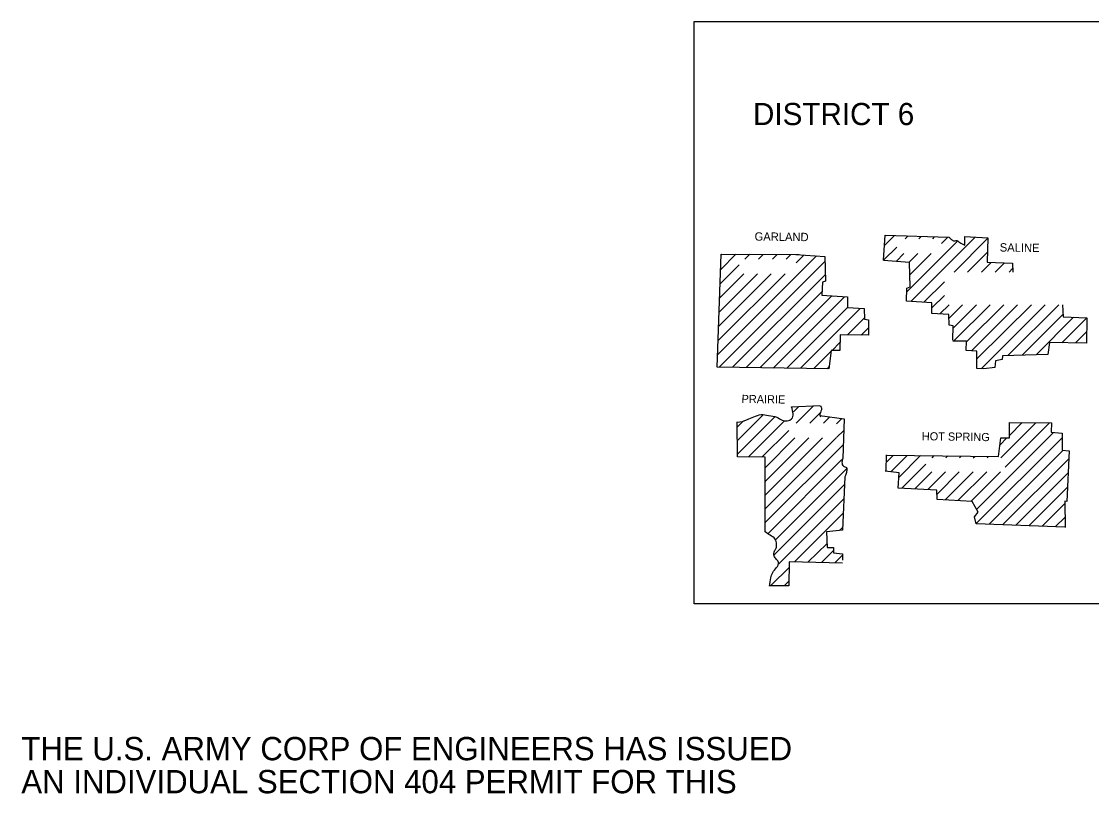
# Model space of a CAD drawing. Extents: x 1366406 to 1373462, y 376856 to 381998.
# Drawn here: x 1371174 to 1371725, y 379841 to 380238 of the extents above; entities that cross this region are included whole.
import ezdxf

# ---------------------------------------------------------------- set-up
doc = ezdxf.new("R2010")
doc.units = 0
doc.layers.add('R_Draft', color=7, linetype='Continuous')

msp = doc.modelspace()

# ---------------------------------------------------------------- linework, layer by layer
at = {"layer": 'R_Draft'}
for p, q in [((1371659.21, 380123.18), (1371659.21, 380127.58)), ((1371625.41, 380005.98), (1371618.31, 380006.68))]:
    msp.add_line(p, q, dxfattribs=at)
msp.add_lwpolyline([(1371519.91, 379938.38), (1371519.91, 380238.38), (1371919.91, 380238.38), (1371919.91, 379938.38)], close=True, dxfattribs=at)
for points in [[(1371617.41, 380115.38), (1371618.31, 380128.28), (1371651.01, 380127.28)], [(1371617.91, 380122.98), (1371623.11, 380128.18)], [(1371628.51, 380126.48), (1371630.01, 380127.98)], [(1371629.41, 380099.08), (1371655.41, 380125.18)], [(1371631.61, 380094.28), (1371664.51, 380127.18)], [(1371635.61, 380126.48), (1371636.71, 380127.68)], [(1371642.71, 380126.48), (1371643.61, 380127.48)], [(1371647.31, 380124.08), (1371650.51, 380127.28)], [(1371653.71, 380109.28), (1371671.01, 380126.58)], [(1371659.21, 380127.58), (1371671.11, 380126.88), (1371670.71, 380114.38), (1371683.81, 380113.88), (1371683.91, 380109.28)], [(1371659.21, 380123.18), (1371659.21, 380123.08)], [(1371531.71, 380060.28), (1371533.91, 380118.58), (1371573.91, 380118.38)], [(1371532.01, 380066.68), (1371582.91, 380117.58)], [(1371533.61, 380110.68), (1371541.41, 380118.48)], [(1371533.91, 380117.98), (1371534.41, 380118.58)], [(1371546.01, 380115.98), (1371548.51, 380118.48)], [(1371553.11, 380115.98), (1371555.51, 380118.38)], [(1371560.21, 380115.98), (1371562.61, 380118.38)], [(1371567.21, 380115.98), (1371569.61, 380118.38)], [(1371572.31, 380118.38), (1371587.21, 380117.28), (1371587.61, 380104.68), (1371585.91, 380104.08), (1371585.71, 380097.38), (1371598.81, 380096.48), (1371598.81, 380090.98), (1371607.51, 380090.48), (1371607.61, 380084.98), (1371609.71, 380084.68), (1371609.61, 380076.78)], [(1371572.41, 380114.08), (1371576.31, 380117.98)], [(1371617.41, 380115.38), (1371624.21, 380122.18)], [(1371623.91, 380114.78), (1371627.91, 380118.78)], [(1371630.51, 380114.28), (1371635.01, 380118.78)], [(1371631.01, 380107.78), (1371642.01, 380118.78)], [(1371660.71, 380109.28), (1371670.81, 380119.38)], [(1371532.71, 380060.28), (1371587.21, 380114.78)], [(1371533.41, 380103.38), (1371543.01, 380112.98)], [(1371653.11, 380074.28), (1371653.21, 380081.68), (1371651.11, 380081.98), (1371651.01, 380087.48), (1371642.31, 380087.98), (1371642.31, 380093.48), (1371629.21, 380094.38), (1371629.41, 380101.08), (1371631.11, 380101.68), (1371630.71, 380114.28), (1371617.41, 380115.28)], [(1371667.91, 380109.28), (1371672.81, 380114.28)], [(1371674.91, 380109.28), (1371679.71, 380114.08)], [(1371532.31, 380073.98), (1371566.71, 380108.38)], [(1371532.51, 380081.28), (1371559.61, 380108.38)], [(1371532.81, 380088.68), (1371552.61, 380108.38)], [(1371533.11, 380095.98), (1371545.51, 380108.38)], [(1371539.71, 380060.28), (1371587.51, 380107.98)], [(1371682.01, 380109.28), (1371683.81, 380111.08)], [(1371638.21, 380093.78), (1371648.71, 380104.28)], [(1371546.71, 380060.08), (1371585.71, 380099.08)], [(1371553.71, 380059.98), (1371590.71, 380097.08)], [(1371560.61, 380059.88), (1371597.31, 380096.58)], [(1371642.31, 380090.88), (1371648.71, 380097.28)], [(1371567.61, 380059.78), (1371598.81, 380090.98)], [(1371574.61, 380059.78), (1371605.41, 380090.58)], [(1371646.41, 380087.78), (1371651.11, 380092.48)], [(1371651.11, 380085.48), (1371658.11, 380092.48)], [(1371653.21, 380080.48), (1371665.21, 380092.48)], [(1371653.51, 380073.68), (1371672.31, 380092.48)], [(1371660.11, 380073.28), (1371679.41, 380092.48)], [(1371662.71, 380068.78), (1371686.41, 380092.48)], [(1371665.51, 380064.58), (1371693.51, 380092.48)], [(1371667.61, 380059.48), (1371700.61, 380092.48)], [(1371681.41, 380066.28), (1371707.61, 380092.48)], [(1371709.51, 380092.48), (1371709.81, 380086.28), (1371722.01, 380085.68), (1371721.91, 380072.68)], [(1371598.81, 380076.88), (1371607.51, 380085.58)], [(1371688.71, 380066.48), (1371709.71, 380087.48)], [(1371696.01, 380066.68), (1371715.21, 380085.98)], [(1371709.21, 380072.78), (1371722.01, 380085.68)], [(1371605.81, 380076.78), (1371609.61, 380080.58)], [(1371609.61, 380076.78), (1371595.01, 380076.98), (1371594.91, 380068.98), (1371590.41, 380068.98), (1371589.31, 380059.48), (1371531.71, 380060.28)], [(1371669.11, 380059.38), (1371665.51, 380059.68), (1371665.51, 380068.48), (1371659.91, 380068.88), (1371660.11, 380073.68), (1371653.11, 380073.78)], [(1371716.21, 380072.78), (1371721.91, 380078.48)], [(1371581.51, 380059.58), (1371590.31, 380068.38)], [(1371590.91, 380068.98), (1371594.91, 380072.98)], [(1371721.91, 380072.68), (1371702.81, 380072.98), (1371701.91, 380066.88), (1371678.61, 380066.18), (1371678.41, 380064.18), (1371675.11, 380063.58), (1371674.71, 380060.18), (1371669.11, 380059.38)], [(1371588.51, 380059.48), (1371589.41, 380060.48)], [(1371570.11, 380039.88), (1371584.61, 380040.58)], [(1371572.41, 380031.48), (1371581.31, 380040.38)], [(1371542.21, 380022.48), (1371555.41, 380035.68)], [(1371542.31, 380015.58), (1371561.51, 380034.78)], [(1371571.11, 380037.28), (1371573.81, 380039.98)], [(1371579.41, 380031.48), (1371585.11, 380037.18)], [(1371584.61, 380035.38), (1371597.11, 380033.78), (1371596.41, 380013.38)], [(1371586.51, 380031.48), (1371589.71, 380034.68)], [(1371542.11, 380029.48), (1371545.31, 380032.68)], [(1371556.51, 379975.48), (1371556.41, 380013.88), (1371542.31, 380014.18), (1371542.11, 380032.08)], [(1371547.91, 380014.08), (1371566.51, 380032.68)], [(1371593.21, 380031.18), (1371596.01, 380033.88)], [(1371619.01, 380014.98), (1371676.61, 380014.38), (1371677.71, 380023.88), (1371682.21, 380023.88), (1371682.31, 380031.88), (1371703.91, 380031.58), (1371703.71, 380026.78), (1371709.31, 380026.38), (1371709.31, 380017.58), (1371712.91, 380017.28), (1371711.71, 379991.08), (1371710.81, 379991.38), (1371710.91, 379977.78)], [(1371677.71, 380013.58), (1371695.81, 380031.68)], [(1371680.01, 380008.88), (1371702.81, 380031.58)], [(1371682.21, 380025.18), (1371688.81, 380031.78)], [(1371554.71, 380013.88), (1371568.61, 380027.78)], [(1371556.41, 380008.48), (1371571.81, 380023.88)], [(1371556.51, 379987.38), (1371593.01, 380023.88)], [(1371556.51, 379994.48), (1371586.01, 380023.88)], [(1371556.51, 380001.48), (1371578.91, 380023.88)], [(1371593.21, 380024.08), (1371596.91, 380027.78)], [(1371665.11, 379979.78), (1371709.31, 380023.98)], [(1371665.31, 379987.08), (1371704.81, 380026.58)], [(1371677.31, 380020.18), (1371680.91, 380023.88)], [(1371556.51, 379980.28), (1371596.61, 380020.38)], [(1371558.01, 379974.68), (1371596.01, 380012.78)], [(1371618.71, 380006.88), (1371619.01, 380015.18)], [(1371618.91, 380011.38), (1371622.51, 380014.98)], [(1371621.11, 380006.48), (1371629.51, 380014.88)], [(1371625.41, 380003.68), (1371636.51, 380014.88)], [(1371642.41, 380013.58), (1371643.51, 380014.78)], [(1371649.41, 380013.58), (1371650.51, 380014.68)], [(1371656.51, 380013.58), (1371657.41, 380014.48)], [(1371663.61, 380013.58), (1371664.41, 380014.38)], [(1371670.71, 380013.58), (1371671.41, 380014.38)], [(1371671.81, 379979.38), (1371709.91, 380017.58)], [(1371678.61, 379979.18), (1371712.71, 380013.18)], [(1371561.91, 379971.48), (1371598.31, 380007.98)], [(1371626.81, 379997.98), (1371639.11, 380010.38)], [(1371597.51, 380003.78), (1371596.31, 379976.38), (1371588.11, 379975.48), (1371588.31, 379967.38), (1371591.61, 379967.48), (1371591.71, 379964.68), (1371596.21, 379964.18), (1371596.31, 379960.88)], [(1371710.91, 379977.98), (1371665.11, 379979.58), (1371664.21, 379983.28), (1371666.11, 379985.68), (1371663.01, 379991.08), (1371645.01, 379992.18), (1371644.91, 379996.98), (1371625.01, 379998.08), (1371625.41, 380005.98)], [(1371633.51, 379997.68), (1371642.21, 380006.38)], [(1371640.21, 379997.28), (1371649.31, 380006.38)], [(1371645.01, 379994.98), (1371656.41, 380006.38)], [(1371649.11, 379991.98), (1371663.51, 380006.38)], [(1371655.71, 379991.58), (1371670.51, 380006.38)], [(1371662.31, 379991.18), (1371677.61, 380006.38)], [(1371685.51, 379978.88), (1371712.31, 380005.78)], [(1371561.01, 379963.58), (1371597.31, 379999.88)], [(1371692.21, 379978.58), (1371712.01, 379998.38)], [(1371563.51, 379958.98), (1371597.01, 379992.48)], [(1371571.61, 379960.08), (1371596.71, 379985.08)], [(1371699.01, 379978.38), (1371710.81, 379990.08)], [(1371705.81, 379978.08), (1371710.91, 379983.08)], [(1371594.81, 379976.18), (1371596.31, 379977.68)], [(1371578.51, 379959.88), (1371588.31, 379969.58)], [(1371585.41, 379959.68), (1371591.71, 379965.98)], [(1371592.31, 379959.48), (1371596.31, 379963.58)], [(1371596.31, 379959.38), (1371568.91, 379960.08), (1371568.71, 379947.78), (1371558.71, 379947.78)], [(1371559.41, 379947.88), (1371569.01, 379957.38)], [(1371566.51, 379947.88), (1371568.71, 379950.08)]]:
    msp.add_lwpolyline(points, dxfattribs=at)
for points in [[(1371651.01, 380127.28), (1371652.21, 380126.18), (1371653.51, 380125.38), (1371655.11, 380125.48), (1371656.61, 380124.58), (1371659.21, 380123.18)], [(1371584.71, 380040.58), (1371585.51, 380038.98), (1371585.21, 380037.58), (1371584.61, 380035.38), (1371585.11, 380034.68)], [(1371542.11, 380031.98), (1371542.21, 380031.98), (1371547.31, 380033.28), (1371550.61, 380034.68), (1371554.41, 380035.88), (1371558.21, 380035.38), (1371562.51, 380034.58), (1371565.21, 380032.98), (1371570.11, 380033.68), (1371570.11, 380039.88)], [(1371596.41, 380013.38), (1371596.01, 380011.38), (1371596.81, 380009.28), (1371598.21, 380008.58), (1371598.41, 380006.58), (1371597.91, 380004.58), (1371597.51, 380003.78)], [(1371558.71, 379947.58), (1371559.41, 379951.78), (1371560.41, 379954.58), (1371562.31, 379957.08), (1371563.41, 379959.78), (1371562.31, 379961.28), (1371561.11, 379963.08), (1371561.31, 379965.58), (1371562.11, 379967.18), (1371562.31, 379969.08), (1371561.61, 379971.78), (1371559.01, 379973.78), (1371556.51, 379975.48)]]:
    msp.add_spline(points, degree=3, dxfattribs=at)

# ---------------------------------------------------------------- texts
for s, height, p in [('DISTRICT 6', 11.4, (1371550.21, 380184.98)), ('THE U.S. ARMY CORP OF ENGINEERS HAS ISSUED', 12, (1371173.57, 379857.87)), ('AN INDIVIDUAL SECTION 404 PERMIT FOR THIS', 12, (1371173.57, 379840.87))]:
    msp.add_text(s, height=height, dxfattribs=at).set_placement(p)
for s, height, rotation, p in [('GARLAND', 4.301, 359.3658, (1371551.01, 380125.48)), ('SALINE', 4.301, 359.1491, (1371677.21, 380119.88)), ('PRAIRIE', 4.201, 359.2116, (1371544.31, 380041.88)), ('HOT SPRING', 4.201, 359.2216, (1371637.11, 380022.68))]:
    msp.add_text(s, height=height, rotation=rotation, dxfattribs=at).set_placement(p)

doc.saveas('drawing.dxf')
